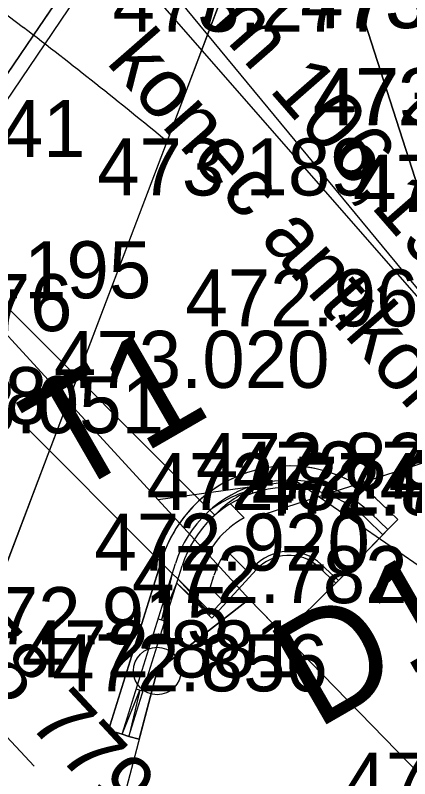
# Model space of a CAD drawing. Extents: x -758836 to -757729, y -1175316 to -1174366.
# Drawn here: x -758396.08 to -758387.77, y -1174860.79 to -1174844.72 of the extents above; entities that cross this region are included whole.
import ezdxf

# ---------------------------------------------------------------- set-up
doc = ezdxf.new("R2010")
doc.units = 0
for name, color, linetype in [('__NOR-dočasný zábor', 7, 'Continuous'), ('__NOR-trvalý zábor', 7, 'Continuous'), ('_NOR-návrh silná', 7, 'Continuous'), ('_NOR-návrh tenká', 7, 'Continuous'), ('_NOR-pomocná', 7, 'Continuous'), ('_NOR-popis', 7, 'Continuous'), ('G_Obvod dráhy', 7, 'Continuous'), ('G_Obvod stavby', 7, 'Continuous'), ('Hranice parcel', 7, 'Continuous'), ('KOS_PZZ nové', 7, 'Continuous'), ('Parcelní čísla', 7, 'Continuous'), ('Vnitřní kresba', 7, 'Continuous'), ('Vrstva 61', 7, 'Continuous'), ('Značky bodu BP', 7, 'Continuous')]:
    doc.layers.add(name, color=color, linetype=linetype)

# ---------------------------------------------------------------- blocks, each defined once
blk = doc.blocks.new('Závora 8m')
for p, q in [((0.083, -0.373), (-0.058, -0.373)), ((-0.058, -0.448), (-0.058, -0.373)), ((1.054, -0.448), (-0.058, -0.448)), ((1.032, -0.373), (0.382, -0.373)), ((0.542, -0.323), (0.542, -1.27)), ((1.149, -0.771), (1.032, -0.373)), ((0.413, -1.026), (1.122, -0.517)), ((0.413, -0.517), (1.122, -1.026)), ((0.767, -0.517), (0.767, -1.026)), ((0.851, -0.571), (5.271, -0.571)), ((0.851, -0.591), (5.271, -0.591)), ((1.751, -0.591), (1.751, -0.951)), ((1.771, -0.591), (1.771, -0.951)), ((2.451, -0.591), (2.451, -0.951)), ((2.471, -0.591), (2.471, -0.951)), ((3.151, -0.591), (3.151, -0.951)), ((3.171, -0.591), (3.171, -0.951)), ((3.851, -0.591), (3.851, -0.951)), ((3.871, -0.591), (3.871, -0.951)), ((4.551, -0.591), (4.551, -0.951)), ((4.571, -0.591), (4.571, -0.951)), ((5.251, -0.591), (5.251, -0.951)), ((5.271, -0.571), (6.851, -0.741)), ((5.271, -0.591), (5.271, -0.951)), ((5.271, -0.591), (6.851, -0.761)), ((1.149, -0.771), (1.032, -1.17)), ((6.851, -0.781), (5.271, -0.951)), ((5.271, -0.971), (6.851, -0.801)), ((5.951, -0.665), (5.951, -0.878)), ((5.971, -0.667), (5.971, -0.876)), ((6.651, -0.74), (6.651, -0.803)), ((6.671, -0.742), (6.671, -0.801)), ((6.851, -0.741), (7.151, -0.741)), ((8.851, -0.761), (6.851, -0.761)), ((6.851, -0.761), (6.851, -0.781)), ((6.851, -0.761), (7.151, -0.761)), ((8.851, -0.781), (6.851, -0.781)), ((6.851, -0.781), (7.151, -0.781)), ((6.851, -0.801), (7.151, -0.801)), ((7.151, -0.741), (7.151, -0.761)), ((7.151, -0.801), (7.151, -0.781)), ((8.851, -0.761), (8.851, -0.781)), ((0.851, -0.951), (5.271, -0.951)), ((1.054, -1.095), (-0.058, -1.095)), ((-0.058, -1.095), (-0.058, -1.17)), ((0.851, -0.971), (5.271, -0.971)), ((0.083, -1.17), (-0.058, -1.17)), ((1.032, -1.17), (0.382, -1.17))]:
    blk.add_line(p, q)
for points in [[(0.382, -0.434), (0.083, -0.434), (0.083, -0.274), (0.382, -0.274)], [(0.382, -0.324), (0.083, -0.324), (0.083, -0.274), (0.382, -0.274)], [(0.413, -0.517), (1.122, -0.517), (1.122, -1.026), (0.413, -1.026)], [(0.382, -1.109), (0.083, -1.109), (0.083, -1.269), (0.382, -1.269)], [(0.382, -1.219), (0.083, -1.219), (0.083, -1.269), (0.382, -1.269)]]:
    blk.add_lwpolyline(points, close=True)
blk.add_lwpolyline([(0.507, -1.048), (0.507, -1.27), (0.578, -1.27), (0.578, -1.048)])
for start, end in [(130.1075, 310.1075), (310.1075, 130.1075)]:
    blk.add_arc((0.767, -0.771), 0.0422, start, end)

msp = doc.modelspace()

# ---------------------------------------------------------------- linework, layer by layer
at = {"layer": '__NOR-dočasný zábor'}
for p, q in [((-758394.04, -1174842.7), (-758395.696, -1174845.14)), ((-758392.028, -1174845.133), (-758391.423, -1174843.542)), ((-758392.882, -1174847.378), (-758392.028, -1174845.133)), ((-758394.966, -1174852.852), (-758392.882, -1174847.378)), ((-758396.673, -1174857.339), (-758394.966, -1174852.852)), ((-758388.338, -1174855.654), (-758389.269, -1174856.616)), ((-758388.234, -1174855.546), (-758388.338, -1174855.654)), ((-758394.114, -1174859.764), (-758392.992, -1174856.172)), ((-758389.269, -1174856.616), (-758389.325, -1174856.673)), ((-758389.325, -1174856.673), (-758390.43, -1174857.749)), ((-758391.15, -1174857.01), (-758393.09, -1174858.52)), ((-758390.43, -1174857.749), (-758391.15, -1174857.01)), ((-758393.09, -1174858.52), (-758393.467, -1174859.955)), ((-758393.827, -1174859.853), (-758394.114, -1174859.764)), ((-758393.684, -1174859.898), (-758393.827, -1174859.853)), ((-758393.467, -1174859.955), (-758393.684, -1174859.898))]:
    msp.add_line(p, q, dxfattribs=at)
for points in [[(-758395.696, -1174845.14), (-758397.65, -1174848.02), (-758397.73, -1174848.137)], [(-758388.372, -1174854.995), (-758388.025, -1174855.331), (-758388.234, -1174855.546)]]:
    msp.add_lwpolyline(points, dxfattribs=at)
for start, end in [(45.9171, 145.2386), (145.2386, 162.6626)]:
    msp.add_arc((-758390.32, -1174857.006), 2.8, start, end, dxfattribs=at)
at = {"layer": '_NOR-návrh silná'}
for p, q in [((-758388.58, -1174855.21), (-758388.234, -1174855.546)), ((-758393.827, -1174859.853), (-758392.706, -1174856.261)), ((-758389.269, -1174856.616), (-758389.641, -1174856.272)), ((-758391.944, -1174857.296), (-758391.056, -1174856.33)), ((-758392.651, -1174856.589), (-758391.944, -1174857.296))]:
    msp.add_line(p, q, dxfattribs=at)
for radius, start, end in [(2.5, 45.9171, 162.6626), (1, 47.2605, 137.4155)]:
    msp.add_arc((-758390.32, -1174857.006), radius, start, end, dxfattribs=at)
at = {"layer": '_NOR-návrh tenká'}
for p, q in [((-758396.571, -1174850.548), (-758391.981, -1174855.138)), ((-758392.771, -1174856.469), (-758396.263, -1174852.977)), ((-758391.122, -1174854.639), (-758391.074, -1174854.781)), ((-758391.549, -1174855.004), (-758391.257, -1174855.296)), ((-758391.981, -1174855.138), (-758391.875, -1174855.244)), ((-758388.685, -1174855.318), (-758388.338, -1174855.654)), ((-758389.325, -1174856.673), (-758388.234, -1174855.546)), ((-758391.621, -1174855.992), (-758391.165, -1174856.449)), ((-758393.684, -1174859.898), (-758392.563, -1174856.306)), ((-758392.771, -1174856.469), (-758392.997, -1174857.446)), ((-758392.771, -1174856.469), (-758392.651, -1174856.589)), ((-758392.332, -1174856.908), (-758392.181, -1174856.425)), ((-758391.942, -1174857.412), (-758390.997, -1174856.384)), ((-758389.325, -1174856.673), (-758389.695, -1174856.331)), ((-758391.972, -1174857.324), (-758392.651, -1174856.589)), ((-758391.975, -1174856.771), (-758391.895, -1174856.515)), ((-758392.997, -1174857.446), (-758392.678, -1174856.675)), ((-758392.678, -1174856.675), (-758391.942, -1174857.412)), ((-758392.678, -1174856.675), (-758391.972, -1174857.324)), ((-758391.975, -1174856.771), (-758391.707, -1174857.038)), ((-758393.069, -1174857.424), (-758392.926, -1174857.468)), ((-758391.944, -1174857.296), (-758392.001, -1174857.353)), ((-758393.827, -1174859.853), (-758393.458, -1174858.921)), ((-758393.458, -1174858.921), (-758393.684, -1174859.898)), ((-758393.529, -1174858.899), (-758393.386, -1174858.943)), ((-758393.827, -1174859.853), (-758393.684, -1174859.898))]:
    msp.add_line(p, q, dxfattribs=at)
for points in [[(-758396.968, -1174857.284), (-758396.673, -1174857.339), (-758390.499, -1174841.114), (-758389.088, -1174839.467), (-758389.316, -1174839.272)], [(-758401.824, -1174840.47), (-758395.906, -1174844.98)], [(-758388.234, -1174855.546), (-758388.025, -1174855.331), (-758388.372, -1174854.995)], [(-758392.992, -1174856.172), (-758394.114, -1174859.764), (-758393.827, -1174859.853)], [(-758393.684, -1174859.898), (-758393.467, -1174859.955), (-758393.09, -1174858.52), (-758391.15, -1174857.01), (-758390.43, -1174857.749), (-758389.325, -1174856.673)]]:
    msp.add_lwpolyline(points, dxfattribs=at)
for centre, radius, start, end in [((-758456.521, -1174924.515), 100, 50.47712, 52.68848), ((-758390.32, -1174857.006), 2.8, 45.9171, 162.6626), ((-758390.32, -1174857.006), 2.35, 45.9171, 162.6626), ((-758390.317, -1174857.442), 2.842, 105.9509, 125.8252), ((-758390.38, -1174856.584), 2.007, 110.9778, 138.1294), ((-758390.32, -1174857.006), 1.95, 118.725, 162.6626), ((-758390.32, -1174857.006), 1.65, 142.0851, 162.6626), ((-758390.32, -1174857.006), 0.92, 47.2605, 137.4155)]:
    msp.add_arc(centre, radius, start, end, dxfattribs=at)
at = {"layer": '_NOR-pomocná'}
for points in [[(-758417.595, -1174755.224), (-758317.652, -1174723.031), (-758272.123, -1174864.38), (-758372.066, -1174896.572)], [(-758517.538, -1174787.416), (-758417.595, -1174755.224), (-758372.066, -1174896.572), (-758472.009, -1174928.764)]]:
    msp.add_lwpolyline(points, close=True, dxfattribs=at)
at = {"layer": '_NOR-popis'}
for p, q in [((-758395.533, -1174841.585), (-758386.352, -1174852.094)), ((-758362.304, -1174846.032), (-758391.059, -1174855.295)), ((-758403.828, -1174851.775), (-758395.679, -1174860.526))]:
    msp.add_line(p, q, dxfattribs=at)
at = {"layer": 'G_Obvod dráhy'}
msp.add_lwpolyline([(-758089.798, -1174768.979), (-758142.696, -1174770.56), (-758184.852, -1174773.129), (-758224.924, -1174775.568), (-758267.901, -1174783.224), (-758300.918, -1174790.499), (-758320.151, -1174797.166), (-758340.173, -1174807.597), (-758368.212, -1174821.896), (-758391.01, -1174838.771), (-758393.792, -1174842.868), (-758397.402, -1174848.189), (-758398.152, -1174849.288), (-758399.482, -1174851.258), (-758414.638, -1174865.002), (-758431.769, -1174880.634), (-758438.551, -1174887.875), (-758457.701, -1174908.335), (-758459.493, -1174910.255), (-758457.797, -1174912.615), (-758465.625, -1174912.295), (-758489.685, -1174938.02), (-758534.085, -1174974.005), (-758544.191, -1174980.324)], dxfattribs=at)
at = {"layer": 'G_Obvod stavby'}
for p, q in [((-758388.338, -1174855.654), (-758389.269, -1174856.616)), ((-758388.234, -1174855.546), (-758388.338, -1174855.654)), ((-758394.114, -1174859.764), (-758392.992, -1174856.172)), ((-758389.269, -1174856.616), (-758389.325, -1174856.673)), ((-758389.325, -1174856.673), (-758390.43, -1174857.749)), ((-758391.15, -1174857.01), (-758393.09, -1174858.52)), ((-758390.43, -1174857.749), (-758391.15, -1174857.01)), ((-758393.09, -1174858.52), (-758393.467, -1174859.955)), ((-758393.827, -1174859.853), (-758394.114, -1174859.764)), ((-758393.684, -1174859.898), (-758393.827, -1174859.853)), ((-758393.467, -1174859.955), (-758393.684, -1174859.898))]:
    msp.add_line(p, q, dxfattribs=at)
for points in [[(-758397.115, -1174857.256), (-758396.673, -1174857.339), (-758394.966, -1174852.852), (-758392.882, -1174847.378), (-758392.028, -1174845.133), (-758391.423, -1174843.542), (-758390.499, -1174841.114), (-758389.088, -1174839.467), (-758389.316, -1174839.272), (-758390.315, -1174838.9)], [(-758388.372, -1174854.995), (-758388.025, -1174855.331), (-758388.234, -1174855.546)]]:
    msp.add_lwpolyline(points, dxfattribs=at)
for start, end in [(45.9171, 145.2386), (145.2386, 162.6626)]:
    msp.add_arc((-758390.32, -1174857.006), 2.8, start, end, dxfattribs=at)
at = {"layer": 'Hranice parcel'}
for points in [[(-758398.4, -1174849.12), (-758397.65, -1174848.02), (-758394.04, -1174842.7)], [(-758394.04, -1174842.7), (-758378.39, -1174861.63), (-758372.47, -1174875.16), (-758371.87, -1174876.54), (-758365.08, -1174901.85)], [(-758391.15, -1174857.01), (-758393.07, -1174854.92), (-758396.15, -1174851.56), (-758397.47, -1174850.13)], [(-758391.15, -1174857.01), (-758393.09, -1174858.52), (-758410.64, -1174925.24)], [(-758365.08, -1174901.85), (-758366.5, -1174900.55), (-758372.65, -1174883.97), (-758377.61, -1174873.09), (-758384.95, -1174863.38), (-758391.15, -1174857.01)]]:
    msp.add_lwpolyline(points, dxfattribs=at)
at = {"layer": 'Vnitřní kresba'}
for p, q in [((-758390.18, -1174854.52), (-758393.07, -1174854.92)), ((-758388.98, -1174855.35), (-758390.18, -1174854.52)), ((-758386.49, -1174857.06), (-758388.98, -1174855.35))]:
    msp.add_line(p, q, dxfattribs=at)
at = {"layer": 'Značky bodu BP'}
for radius in [0.5, 0.0303]:
    msp.add_circle((-758393.09, -1174858.52), radius, dxfattribs=at)

# ---------------------------------------------------------------- block references
at = {"layer": 'KOS_PZZ nové', "rotation": -138.39048976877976}
msp.add_blockref('Závora 8m', (-758392.291, -1174840.194), dxfattribs=at)

# ---------------------------------------------------------------- texts
at = {"layer": '__NOR-dočasný zábor'}
msp.add_text('D1', height=2.2727, rotation=30, dxfattribs=at).set_placement((-758389.741, -1174859.768))
at = {"layer": '__NOR-trvalý zábor'}
msp.add_text('T1', height=2.2727, rotation=30, dxfattribs=at).set_placement((-758394.988, -1174854.882))
at = {"layer": '_NOR-popis'}
for s, rotation, p in [('km 106,191 956', 311.1419, (-758392.525, -1174844.268)), ('konec antikorozní úpravy upevňovadel', 311.1419, (-758394.182, -1174845.716)), ('km 106,178 779', 312.9634, (-758402.099, -1174852.898)), ('začátek antikorozní úpravy upevňovadel', 312.9634, (-758403.709, -1174854.398))]:
    msp.add_text(s, height=1.25, rotation=rotation, dxfattribs=at).set_placement(p)
at = {"layer": 'Parcelní čísla'}
msp.add_text('2677/6', height=1.7, rotation=340, dxfattribs=at).set_placement((-758391.627, -1174842.978))
at = {"layer": 'Vrstva 61'}
for s, p in [('473.001', (-758390.078, -1174844.994)), ('473.077', (-758390.055, -1174844.99)), ('473.277', (-758394.029, -1174845.067)), ('472.982', (-758389.813, -1174847.04)), ('473.051', (-758389.779, -1174847.031)), ('473.541', (-758400.4, -1174847.707)), ('473.189', (-758394.354, -1174848.514)), ('472.935', (-758388.967, -1174848.86)), ('472.991', (-758388.942, -1174848.857)), ('473.195', (-758399.015, -1174850.678)), ('472.968', (-758392.496, -1174851.269)), ('473.276', (-758400.675, -1174851.369)), ('473.020', (-758395.262, -1174852.563)), ('473.328', (-758401.205, -1174853.326)), ('473.051', (-758398.748, -1174853.517)), ('472.828', (-758392.274, -1174854.711)), ('472.775', (-758391.501, -1174854.893)), ('472.874', (-758393.314, -1174855.135)), ('472.830', (-758391.104, -1174855.25)), ('472.744', (-758391.068, -1174855.208)), ('472.920', (-758394.412, -1174856.409)), ('472.782', (-758393.618, -1174857.093)), ('472.915', (-758397.379, -1174857.956)), ('472.881', (-758395.939, -1174858.657)), ('472.856', (-758395.297, -1174858.949)), ('472.173', (-758389.168, -1174861.437))]:
    msp.add_text(s, height=1.2, dxfattribs=at).set_placement(p)

doc.saveas('drawing.dxf')
